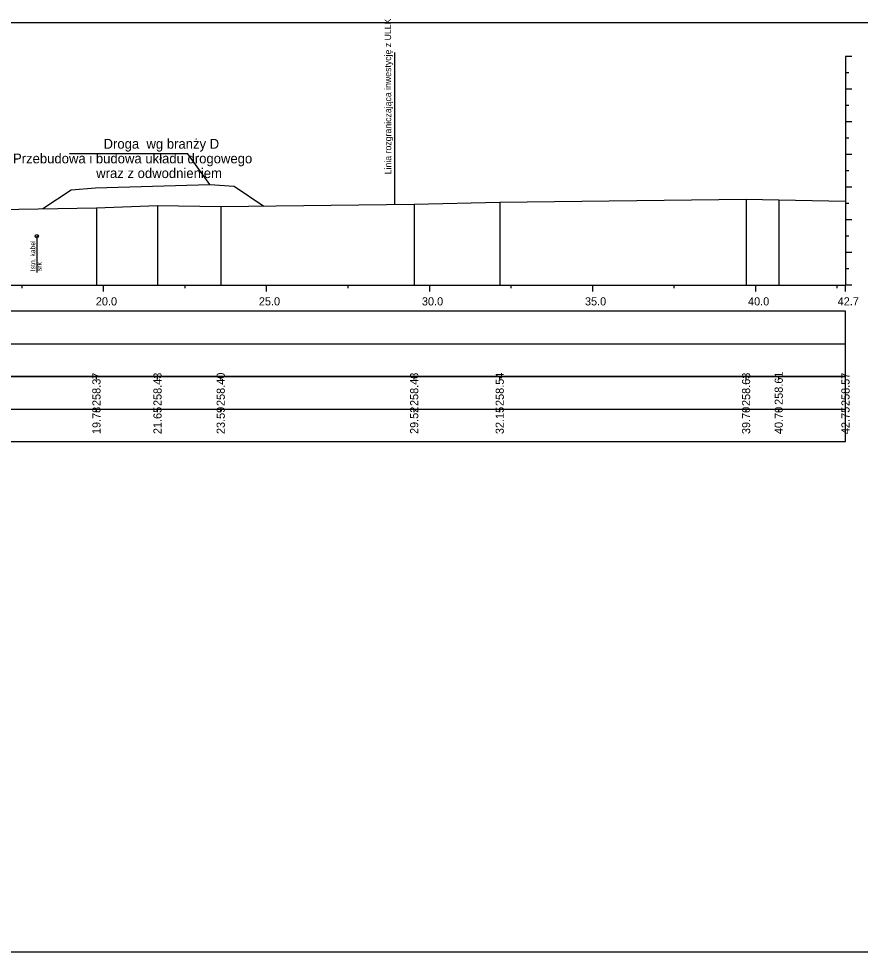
# Model space of a CAD drawing. Extents: x 6516023 to 6560129, y 5513077 to 5529206.
# Drawn here: x 6516782.61 to 6516808.42, y 5514518.16 to 5514546.77 of the extents above; entities that cross this region are included whole.
import ezdxf

# ---------------------------------------------------------------- set-up
doc = ezdxf.new("R2010")
doc.units = 0
for name, color, linetype in [('TOR_PRZEK_P-inne branze', 7, 'Continuous'), ('TOR_PRZEK_P-kable', 7, 'Continuous'), ('TOR_PRZEK_P-tabelka istniejace', 7, 'Continuous'), ('TOR_PRZEK_P-tabelka projektowane', 7, 'Continuous'), ('TOR_PRZEK_P-teren istniejacy', 7, 'Continuous'), ('TOR_PRZEK_P-uklad odniesienia', 7, 'Continuous'), ('TOR_PS_T-granica PKP-projektowana', 7, 'Continuous'), ('TOR_RAMKI-ramka+tabelka 1', 7, 'Continuous')]:
    doc.layers.add(name, color=color, linetype=linetype)

msp = doc.modelspace()

# ---------------------------------------------------------------- linework, layer by layer
at = {"layer": 'TOR_PRZEK_P-inne branze'}
for p, q in [((6516787.791, 5514542.625), (6516784.166, 5514542.625)), ((6516788.467, 5514541.691), (6516787.791, 5514542.625))]:
    msp.add_line(p, q, dxfattribs=at)
msp.add_lwpolyline([(6516783.348, 5514540.947), (6516784.217, 5514541.526), (6516784.967, 5514541.586), (6516786.717, 5514541.638), (6516788.467, 5514541.691), (6516789.217, 5514541.631), (6516790.125, 5514541.025)], dxfattribs=at)
at = {"layer": 'TOR_PRZEK_P-kable'}
msp.add_line((6516783.163, 5514540.104), (6516783.163, 5514538.994), dxfattribs=at)
msp.add_circle((6516783.163, 5514540.104), 0.05, dxfattribs=at)
at = {"layer": 'TOR_PRZEK_P-tabelka istniejace'}
for p, q in [((6516784.993, 5514535.706), (6516784.993, 5514535.806)), ((6516786.865, 5514535.706), (6516786.865, 5514535.806)), ((6516788.804, 5514535.706), (6516788.804, 5514535.806)), ((6516794.737, 5514535.706), (6516794.737, 5514535.806)), ((6516797.36, 5514535.706), (6516797.36, 5514535.806)), ((6516804.915, 5514535.706), (6516804.915, 5514535.806)), ((6516805.916, 5514535.706), (6516805.916, 5514535.806)), ((6516807.963, 5514535.706), (6516807.963, 5514535.806)), ((6516724.163, 5514534.806), (6516807.963, 5514534.806)), ((6516784.993, 5514534.706), (6516784.993, 5514534.806)), ((6516786.865, 5514534.706), (6516786.865, 5514534.806)), ((6516788.804, 5514534.706), (6516788.804, 5514534.806)), ((6516794.737, 5514534.706), (6516794.737, 5514534.806)), ((6516797.36, 5514534.706), (6516797.36, 5514534.806)), ((6516804.915, 5514534.706), (6516804.915, 5514534.806)), ((6516805.916, 5514534.706), (6516805.916, 5514534.806)), ((6516807.963, 5514534.706), (6516807.963, 5514534.806))]:
    msp.add_line(p, q, dxfattribs=at)
for points in [[(6516804.915, 5514541.241), (6516804.915, 5514538.806), (6516804.915, 5514538.676), (6516804.915, 5514538.606)], [(6516805.916, 5514541.213), (6516805.916, 5514538.806), (6516805.916, 5514538.676), (6516805.916, 5514538.606)], [(6516807.963, 5514541.181), (6516807.963, 5514538.806), (6516807.963, 5514538.676), (6516807.963, 5514538.606)], [(6516784.993, 5514540.976), (6516784.993, 5514538.806), (6516784.993, 5514538.676), (6516784.993, 5514538.606)], [(6516786.865, 5514541.039), (6516786.865, 5514538.806), (6516786.865, 5514538.676), (6516786.865, 5514538.606)], [(6516788.804, 5514541.008), (6516788.804, 5514538.806), (6516788.804, 5514538.676), (6516788.804, 5514538.606)], [(6516794.737, 5514541.087), (6516794.737, 5514538.806), (6516794.737, 5514538.676), (6516794.737, 5514538.606)], [(6516797.36, 5514541.143), (6516797.36, 5514538.806), (6516797.36, 5514538.676), (6516797.36, 5514538.606)]]:
    msp.add_lwpolyline(points, dxfattribs=at)
msp.add_lwpolyline([(6516724.163, 5514535.806), (6516724.163, 5514533.806), (6516807.963, 5514533.806), (6516807.963, 5514535.806)], close=True, dxfattribs=at)
at = {"layer": 'TOR_PRZEK_P-tabelka projektowane'}
msp.add_line((6516724.163, 5514536.806), (6516807.963, 5514536.806), dxfattribs=at)
msp.add_lwpolyline([(6516724.163, 5514537.806), (6516724.163, 5514535.806), (6516807.963, 5514535.806), (6516807.963, 5514537.806)], close=True, dxfattribs=at)
at = {"layer": 'TOR_PRZEK_P-teren istniejacy'}
msp.add_lwpolyline([(6516782.011, 5514540.923), (6516784.993, 5514540.976), (6516786.865, 5514541.039), (6516788.804, 5514541.008), (6516794.737, 5514541.087), (6516797.36, 5514541.143), (6516804.915, 5514541.241), (6516805.916, 5514541.213), (6516807.963, 5514541.181)], dxfattribs=at)
at = {"layer": 'TOR_PRZEK_P-uklad odniesienia'}
for p, q in [((6516807.963, 5514545.606), (6516807.963, 5514538.606)), ((6516808.163, 5514545.606), (6516807.963, 5514545.606)), ((6516808.063, 5514545.106), (6516807.963, 5514545.106)), ((6516808.163, 5514544.606), (6516807.963, 5514544.606)), ((6516808.063, 5514544.106), (6516807.963, 5514544.106)), ((6516808.163, 5514543.606), (6516807.963, 5514543.606)), ((6516808.063, 5514543.106), (6516807.963, 5514543.106)), ((6516808.163, 5514542.606), (6516807.963, 5514542.606)), ((6516808.063, 5514542.106), (6516807.963, 5514542.106)), ((6516808.163, 5514541.606), (6516807.963, 5514541.606)), ((6516808.063, 5514541.106), (6516807.963, 5514541.106)), ((6516808.163, 5514540.606), (6516807.963, 5514540.606)), ((6516808.063, 5514540.106), (6516807.963, 5514540.106)), ((6516808.163, 5514539.606), (6516807.963, 5514539.606)), ((6516808.063, 5514539.106), (6516807.963, 5514539.106)), ((6516727.963, 5514538.606), (6516807.963, 5514538.606)), ((6516782.713, 5514538.506), (6516782.713, 5514538.606)), ((6516785.213, 5514538.406), (6516785.213, 5514538.606)), ((6516787.713, 5514538.506), (6516787.713, 5514538.606)), ((6516790.213, 5514538.406), (6516790.213, 5514538.606)), ((6516792.713, 5514538.506), (6516792.713, 5514538.606)), ((6516795.213, 5514538.406), (6516795.213, 5514538.606)), ((6516797.713, 5514538.506), (6516797.713, 5514538.606)), ((6516800.213, 5514538.406), (6516800.213, 5514538.606)), ((6516802.713, 5514538.506), (6516802.713, 5514538.606)), ((6516805.213, 5514538.406), (6516805.213, 5514538.606)), ((6516807.713, 5514538.506), (6516807.713, 5514538.606)), ((6516807.963, 5514538.406), (6516807.963, 5514538.606)), ((6516808.163, 5514538.606), (6516807.963, 5514538.606))]:
    msp.add_line(p, q, dxfattribs=at)
at = {"layer": 'TOR_PS_T-granica PKP-projektowana'}
msp.add_line((6516794.144, 5514541.079), (6516794.144, 5514545.736), dxfattribs=at)
at = {"layer": 'TOR_RAMKI-ramka+tabelka 1'}
msp.add_lwpolyline([(6516634.513, 5514546.656), (6516882.013, 5514546.656), (6516882.013, 5514518.156), (6516634.513, 5514518.156)], close=True, dxfattribs=at)

# ---------------------------------------------------------------- texts
at = {"layer": 'TOR_PRZEK_P-inne branze'}
for s, p in [('Droga  wg branży D', (6516785.211, 5514542.785)), ('Przebudowa i budowa układu drogowego', (6516782.433, 5514542.335)), ('wraz z odwodnieniem ', (6516784.985, 5514541.885))]:
    msp.add_text(s, height=0.3, dxfattribs=at).set_placement(p)
at = {"layer": 'TOR_PRZEK_P-kable'}
for s, height, p in [('Istn. kabel', 0.14999, (6516783.117, 5514539.03)), ('srk', 0.15, (6516783.312, 5514539.031))]:
    msp.add_text(s, height=height, rotation=90.0511, dxfattribs=at).set_placement(p)
at = {"layer": 'TOR_PRZEK_P-tabelka istniejace'}
for s, p in [('258.37', (6516785.118, 5514534.898)), ('258.43', (6516786.99, 5514534.898)), ('258.40', (6516788.929, 5514534.898)), ('258.48', (6516794.862, 5514534.898)), ('258.54', (6516797.485, 5514534.899)), ('258.63', (6516805.04, 5514534.898)), ('258.61', (6516806.041, 5514534.933)), ('258.57', (6516808.088, 5514534.898)), ('19.78', (6516785.118, 5514534.038)), ('21.65', (6516786.99, 5514534.037)), ('23.59', (6516788.929, 5514534.038)), ('29.52', (6516794.862, 5514534.04)), ('32.15', (6516797.485, 5514534.037)), ('39.70', (6516805.04, 5514534.038)), ('40.70', (6516806.041, 5514534.038)), ('42.75', (6516808.088, 5514534.037))]:
    msp.add_text(s, height=0.25, rotation=90, dxfattribs=at).set_placement(p)
at = {"layer": 'TOR_PRZEK_P-uklad odniesienia'}
for s, p in [('20.0', (6516784.974, 5514537.981)), ('25.0', (6516789.974, 5514537.981)), ('30.0', (6516794.974, 5514537.981)), ('35.0', (6516799.974, 5514537.981)), ('40.0', (6516804.974, 5514537.981)), ('42.7', (6516807.724, 5514537.981))]:
    msp.add_text(s, height=0.25, dxfattribs=at).set_placement(p)
at = {"layer": 'TOR_PS_T-granica PKP-projektowana'}
msp.add_text('Linia rozgraniczająca inwestycję z ULLK', height=0.2, rotation=90.0511, dxfattribs=at).set_placement((6516794.033, 5514542))

doc.saveas('drawing.dxf')
